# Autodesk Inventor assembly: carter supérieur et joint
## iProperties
Author: chr
Created: 2002-03
Part Number: carter supérieur et joint
Document SubType Name: Assemblage
Designer: chr
Control State: 0
Master: False
Checked Out: False
PropertySet Name: Design Tracking Control
Shininess: 41.0
Angle Display Precision: 2
Document Length Units: 11269
Document Angle Units: 11283
Document Time Units: 11279
Document Mass Units: 11290
Document Length Units Precision: 3
Document Angle Units Precision: 2
Compacted: False
PropertySet Name: _Private Model Information
Density: 0.0
Volumn: 0.0
Area: 0.0
PropertySet Name: Model Information
